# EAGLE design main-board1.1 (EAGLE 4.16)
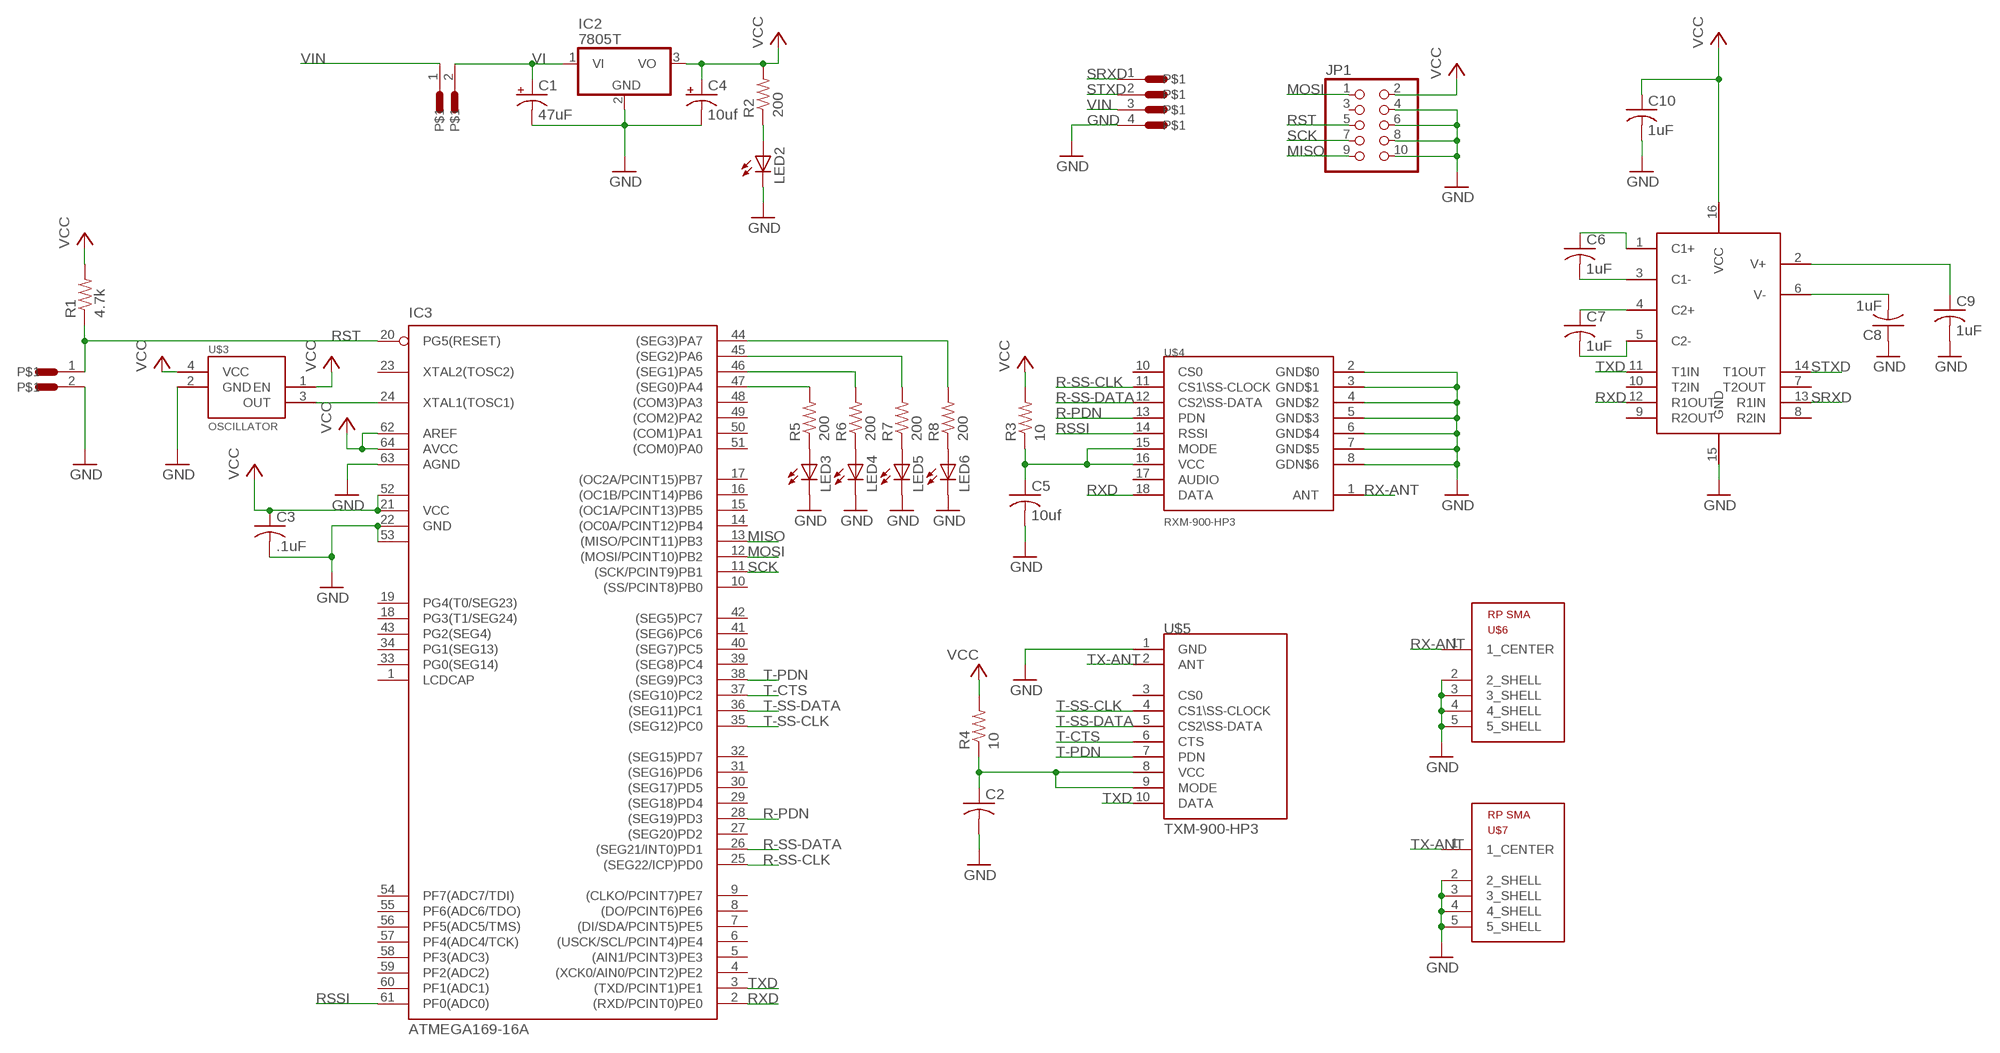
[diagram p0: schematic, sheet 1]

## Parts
C1  47uF  CPOL-USE  [PANASONIC_E]
C2  C-USC1206  [C1206]
C3  .1uF  C-USC0603  [C0603]
C4  10uf  CPOL-USB  [PANASONIC_B]
C5  10uf  C-USC1206  [C1206]
C6  1uF  C-USC0603  [C0603]
C7  1uF  C-USC0603  [C0603]
C8  1uF  C-USC0603  [C0603]
C9  1uF  C-USC0603  [C0603]
C10  1uF  C-USC0603  [C0603]
IC2  7805T  [TO220H]
IC3  ATMEGA169-16A  [TQFP64]
JP1  PINHD-2X5  [2X05]
LED2  LED5MM  [LED5MM]
LED3  LED5MM  [LED5MM]
LED4  LED5MM  [LED5MM]
LED5  LED5MM  [LED5MM]
LED6  LED5MM  [LED5MM]
R1  4.7k  R-US_R0603  [R0603]
R2  200  R-US_R0603  [R0603]
R3  10  R-US_R0603  [R0603]
R4  10  R-US_R0603  [R0603]
R5  200  R-US_R0603  [R0603]
R6  200  R-US_R0603  [R0603]
R7  200  R-US_R0603  [R0603]
R8  200  R-US_R0603  [R0603]
U$1  JST_PA_2  [JST_PA_2]
U$2  JST_PA_2  [JST_PA_2]
U$3  OSCILLATOR  [7X5MM]
U$4  RXM-900-HP3  [RXM-900-HP3]
U$5  TXM-900-HP3  [TXM-900-HP3]
U$6  RP_SMA_TH  [RPSMA_TH]
U$7  RP_SMA_TH  [RPSMA_TH]
U$8  JST_PA_4  [JST_PA_4]
U$9  MAX232-SO16  [SO16]

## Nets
GND: C1.- C2.2 C3.2 C4.- C5.2 C8.1 C9.2 C10.2 IC2.2(GND) IC3.22(GND) IC3.53(GND1) IC3.63(AGND) JP1.4 JP1.6 JP1.8 JP1.10 LED2.K(C) LED3.K(C) LED4.K(C) LED5.K(C) LED6.K(C) U$1.2 U$3.2(GND) U$4.2(GND$0) U$4.3(GND$1) U$4.4(GND$2) U$4.5(GND$3) U$4.6(GND$4) U$4.7(GND$5) U$4.8(GDN$6) U$5.1(GND) U$6.2(2_SHELL) U$6.3(3_SHELL) U$6.4(4_SHELL) U$6.5(5_SHELL) U$7.2(2_SHELL) U$7.3(3_SHELL) U$7.4(4_SHELL) U$7.5(5_SHELL) U$8.4 U$9.15(GND)
MISO: IC3.13((MISO/PCINT11)PB3) JP1.9
MOSI: IC3.12((MOSI/PCINT10)PB2) JP1.1
N$1: LED2.A R2.1
N$2: C6.1 U$9.1(C1+)
N$3: C6.2 U$9.3(C1-)
N$4: C7.1 U$9.4(C2+)
N$5: C7.2 U$9.5(C2-)
N$6: C9.1 U$9.2(V+)
N$7: C8.2 U$9.6(V-)
N$8: LED3.A R5.1
N$9: C2.1 R4.1 U$5.8(VCC) U$5.9(MODE)
N$10: LED4.A R6.1
N$11: LED5.A R7.1
N$12: C5.1 R3.1 U$4.15(MODE) U$4.16(VCC)
N$13: LED6.A R8.1
N$14: IC3.47((SEG0)PA4) R5.2
N$15: IC3.46((SEG1)PA5) R6.2
N$16: IC3.45((SEG2)PA6) R7.2
N$17: IC3.44((SEG3)PA7) R8.2
N$18: IC3.24(XTAL1(TOSC1)) U$3.3(OUT)
R-PDN: IC3.28((SEG19)PD3) U$4.13(PDN)
R-SS-CLK: IC3.25((SEG22/ICP)PD0) U$4.11(CS1\SS-CLOCK)
R-SS-DATA: IC3.26((SEG21/INT0)PD1) U$4.12(CS2\SS-DATA)
RSSI: IC3.61(PF0(ADC0)) U$4.14(RSSI)
RST: IC3.20(PG5(RESET)) JP1.5 R1.1 U$1.1
RX-ANT: U$4.1(ANT) U$6.1(1_CENTER)
RXD: IC3.2((RXD/PCINT0)PE0) U$4.18(DATA) U$9.12(R1OUT)
SCK: IC3.11((SCK/PCINT9)PB1) JP1.7
SRXD: U$8.1 U$9.13(R1IN)
STXD: U$8.2 U$9.14(T1OUT)
T-CTS: IC3.37((SEG10)PC2) U$5.6(CTS)
T-PDN: IC3.38((SEG9)PC3) U$5.7(PDN)
T-SS-CLK: IC3.35((SEG12)PC0) U$5.4(CS1\SS-CLOCK)
T-SS-DATA: IC3.36((SEG11)PC1) U$5.5(CS2\SS-DATA)
TX-ANT: U$5.2(ANT) U$7.1(1_CENTER)
TXD: IC3.3((TXD/PCINT1)PE1) U$5.10(DATA) U$9.11(T1IN)
VCC: C3.1 C4.+ C10.1 IC2.3(VO) IC3.21(VCC) IC3.52(VCC1) IC3.62(AREF) IC3.64(AVCC) JP1.2 R1.2 R2.2 R3.2 R4.2 U$3.1(EN) U$3.4(VCC) U$9.16(VCC)
VI: C1.+ IC2.1(VI) U$2.2
VIN: U$2.1 U$8.3
Unconnected: IC3.1(LCDCAP) IC3.4((XCK0/AIN0/PCINT2)PE2) IC3.5((AIN1/PCINT3)PE3) IC3.6((USCK/SCL/PCINT4)PE4) IC3.7((DI/SDA/PCINT5)PE5) IC3.8((DO/PCINT6)PE6) IC3.9((CLKO/PCINT7)PE7) IC3.10((SS/PCINT8)PB0) IC3.14((OC0A/PCINT12)PB4) IC3.15((OC1A/PCINT13)PB5) IC3.16((OC1B/PCINT14)PB6) IC3.17((OC2A/PCINT15)PB7) IC3.18(PG3(T1/SEG24)) IC3.19(PG4(T0/SEG23)) IC3.23(XTAL2(TOSC2)) IC3.27((SEG20)PD2) IC3.29((SEG18)PD4) IC3.30((SEG17)PD5) IC3.31((SEG16)PD6) IC3.32((SEG15)PD7) IC3.33(PG0(SEG14)) IC3.34(PG1(SEG13)) IC3.39((SEG8)PC4) IC3.40((SEG7)PC5) IC3.41((SEG6)PC6) IC3.42((SEG5)PC7) IC3.43(PG2(SEG4)) IC3.48((COM3)PA3) IC3.49((COM2)PA2) IC3.50((COM1)PA1) IC3.51((COM0)PA0) IC3.54(PF7(ADC7/TDI)) IC3.55(PF6(ADC6/TDO)) IC3.56(PF5(ADC5/TMS)) IC3.57(PF4(ADC4/TCK)) IC3.58(PF3(ADC3)) IC3.59(PF2(ADC2)) IC3.60(PF1(ADC1)) JP1.3 U$4.10(CS0) U$4.17(AUDIO) U$5.3(CS0) U$9.7(T2OUT) U$9.8(R2IN) U$9.9(R2OUT) U$9.10(T2IN)

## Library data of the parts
C1 C4 = rcl:CPOL-US: POLARIZED CAPACITOR, American symbol
C2 C3 C5-C10 = rcl:C-US: CAPACITOR, American symbol
IC2 = linear:78*: Positive VOLTAGE REGULATOR Source: http://cache.national.com/ds/LM/LM78L05.pdf http://www.fairchildsemi.com/ds/LM/LM7805.pdf
IC3 = avr:ATMEGA169: MICROCONTROLLER 16 Kbytes FLASH 1 Kbytes SRAM 512 bytes EEPROM USART 8-channel 10 bit ADC 4x25 Segment LCD Driver
JP1 = pinhead:PINHD-2X5: PIN HEADER
LED2-LED6 = led:LED: LED
R1-R8 = rcl:R-US_: RESISTOR, American symbol
U$1 U$2 = jst_pa:JST_PA_2
U$3 = misc-personal:OSCILLATOR
U$4 = HP3:RXM-900-HP3
U$5 = HP3:TXM-900-HP3
U$6 U$7 = linx:RP_SMA_TH
U$8 = jst_pa:JST_PA_4
U$9 = max232:MAX232-SO16

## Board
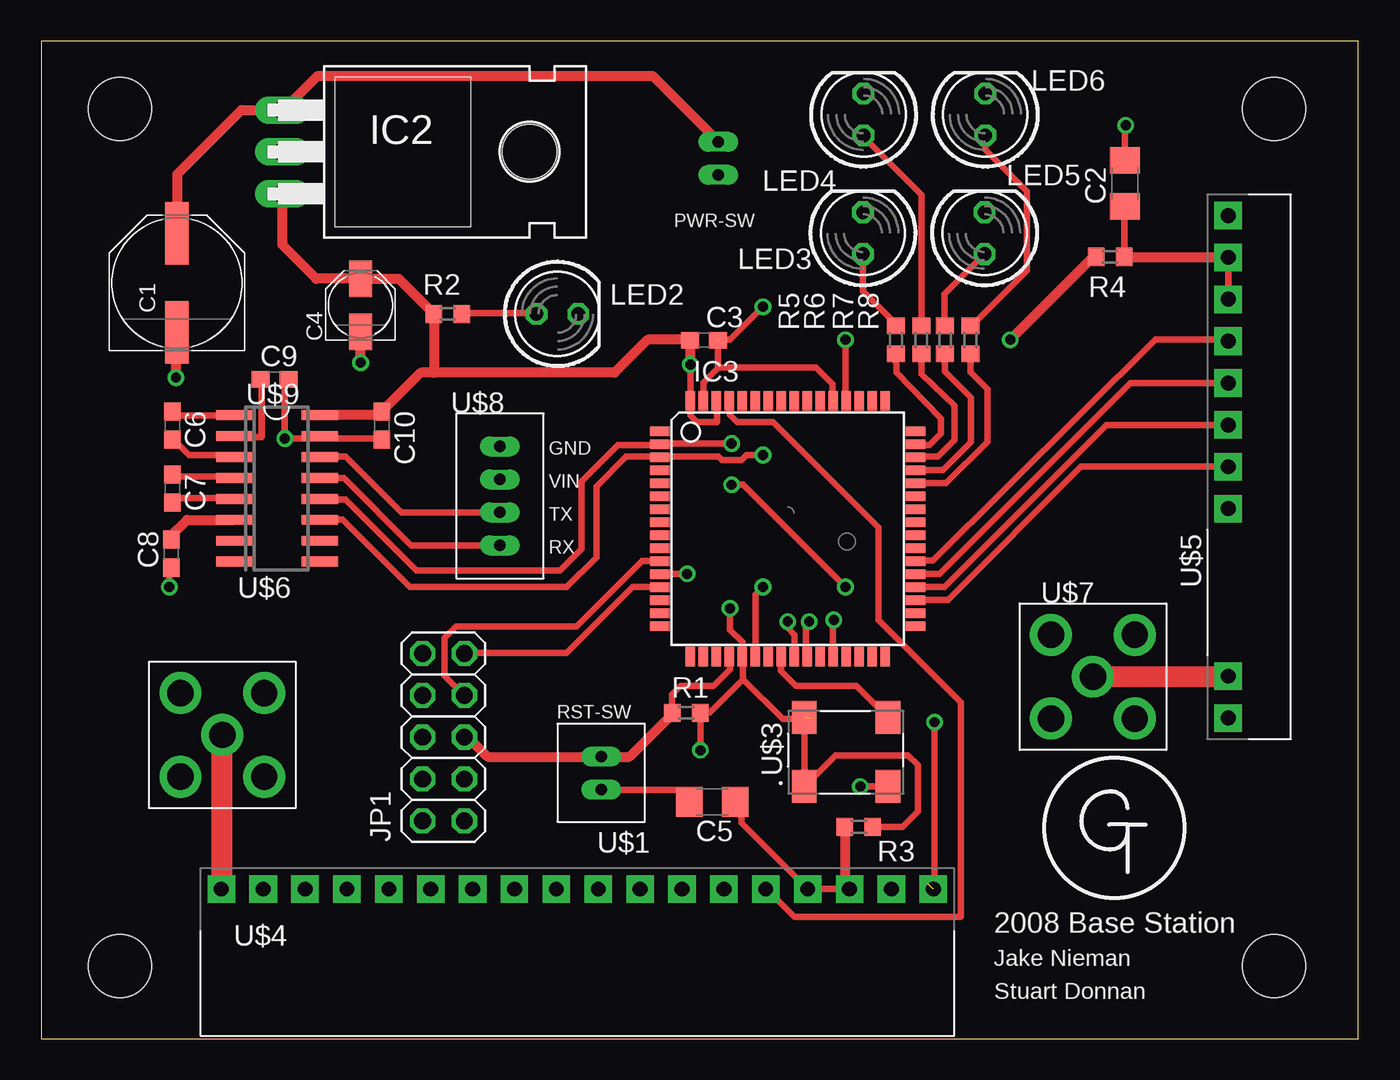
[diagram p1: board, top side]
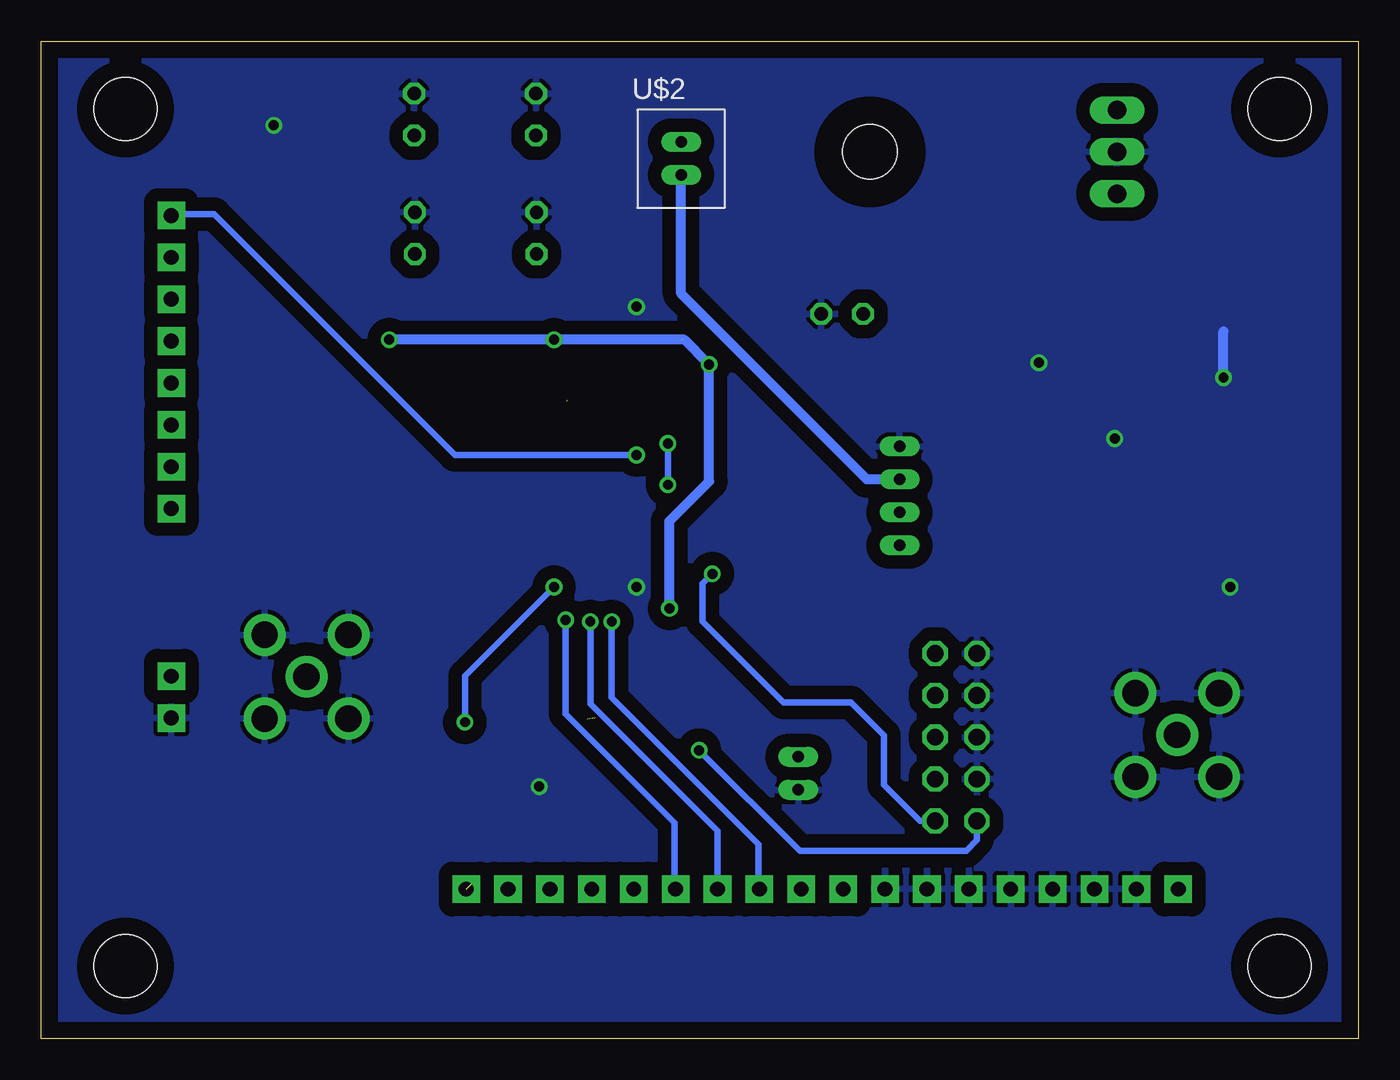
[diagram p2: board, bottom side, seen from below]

Size 79.87 x 60.49 mm. Coordinates in mm from the lower left corner, seen from the top.
Outline: 0,0 79.87,0 79.87,60.49 0,60.49 0,0
Copper layers (1*16): Top 0.035mm / dielectric 1.5mm / Bottom 0.035mm
Design rules "4pcb": minimum track width 6mil, minimum drill 15mil, track to track 6mil, track to pad 6mil, pad to pad 6mil, via to via 6mil, smd to smd 6mil, copper to edge 40mil, drill to drill 6mil, minimum pad ring 10mil, minimum via ring 8mil, stop-mask expansion 6mil, vias tented up to drill 0mil, thermal gap 10mil
Holes 3.82 mm at 4.77,56.39 4.77,4.39 74.77,4.39 74.77,56.39

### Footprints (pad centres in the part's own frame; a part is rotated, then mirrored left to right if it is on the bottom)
PANASONIC_E = smd 3.8 x 1.4: + 3,0; - -3,0
C1206 = smd 1.6 x 1.8: 1 -1.4,0; 2 1.4,0
C0603 = smd 1.1 x 1: 1 -0.85,0; 2 0.85,0
PANASONIC_B = smd 2.2 x 1.4: + 1.6,0; - -1.6,0
TO220H = drill 1.118 long: 1 -2.54,-10.16; 2 0,-10.16; 3 2.54,-10.16 | hole 3.302: 0,4.826
TQFP64 = smd 1.194 x 0.559: 1 -7.76,5.905; 2 -7.76,5.118; 3 -7.76,4.331; 4 -7.76,3.543; 5 -7.76,2.756; 6 -7.76,1.968; 7 -7.76,1.181; 8 -7.76,0.394; 9 -7.76,-0.394; 10 -7.76,-1.181; 11 -7.76,-1.968; 12 -7.76,-2.756; 13 -7.76,-3.543; 14 -7.76,-4.331; 15 -7.76,-5.118; 16 -7.76,-5.905; 33 7.76,-5.905; 34 7.76,-5.118; 35 7.76,-4.331; 36 7.76,-3.543; 37 7.76,-2.756; 38 7.76,-1.968; 39 7.76,-1.181; 40 7.76,-0.394; 41 7.76,0.394; 42 7.76,1.181; 43 7.76,1.968; 44 7.76,2.756; 45 7.76,3.543; 46 7.76,4.331; 47 7.76,5.118; 48 7.76,5.905 | smd 0.559 x 1.194: 17 -5.905,-7.76; 18 -5.118,-7.76; 19 -4.331,-7.76; 20 -3.543,-7.76; 21 -2.756,-7.76; 22 -1.968,-7.76; 23 -1.181,-7.76; 24 -0.394,-7.76; 25 0.394,-7.76; 26 1.181,-7.76; 27 1.968,-7.76; 28 2.756,-7.76; 29 3.543,-7.76; 30 4.331,-7.76; 31 5.118,-7.76; 32 5.905,-7.76; 49 5.905,7.76; 50 5.118,7.76; 51 4.331,7.76; 52 3.543,7.76; 53 2.756,7.76; 54 1.968,7.76; 55 1.181,7.76; 56 0.394,7.76; 57 -0.394,7.76; 58 -1.181,7.76; 59 -1.968,7.76; 60 -2.756,7.76; 61 -3.543,7.76; 62 -4.331,7.76; 63 -5.118,7.76; 64 -5.905,7.76
2X05 = drill 1.016 octagon: 1 -5.08,-1.27; 2 -5.08,1.27; 3 -2.54,-1.27; 4 -2.54,1.27; 5 0,-1.27; 6 0,1.27; 7 2.54,-1.27; 8 2.54,1.27; 9 5.08,-1.27; 10 5.08,1.27
LED5MM = drill 0.813 octagon: A -1.27,0; K 1.27,0
R0603 = smd 1 x 1.1: 1 -0.85,0; 2 0.85,0
JST_PA_2 = drill 0.7 long: 1 13.35,0; 2 11.35,0
7X5MM = smd 1.5 x 2: 1 0,-4.2; 2 5.08,-4.2; 3 5.08,0; 4 0,0
RXM-900-HP3 = drill 0.9 pad 1.676 square: 1 0,0; 2 2.54,0; 3 5.08,0; 4 7.62,0; 5 10.16,0; 6 12.7,0; 7 15.24,0; 8 17.78,0; 9 20.32,0; 10 22.86,0; 11 25.4,0; 12 27.94,0; 13 30.48,0; 14 33.02,0; 15 35.56,0; 16 38.1,0; 17 40.64,0; 18 43.18,0
TXM-900-HP3 = drill 0.9 pad 1.676 square: 1 0,0; 2 2.54,0; 3 12.7,0; 4 15.24,0; 5 17.78,0; 6 20.32,0; 7 22.86,0; 8 25.4,0; 9 27.94,0; 10 30.48,0
RPSMA_TH = drill 1.6 pad 2.54 round: 1 0,0; 2 2.54,2.54; 3 2.54,-2.54; 4 -2.54,-2.54; 5 -2.54,2.54
JST_PA_4 = drill 0.7 long: 1 3,0; 2 1,0; 3 -1,0; 4 -3,0
SO16 = smd 0.6 x 2.2: 1 -4.445,-2.6; 2 -3.175,-2.6; 3 -1.905,-2.6; 4 -0.635,-2.6; 5 0.635,-2.6; 6 1.905,-2.6; 7 3.175,-2.6; 8 4.445,-2.6; 9 4.445,2.6; 10 3.175,2.6; 11 1.905,2.6; 12 0.635,2.6; 13 -0.635,2.6; 14 -1.905,2.6; 15 -3.175,2.6; 16 -4.445,2.6

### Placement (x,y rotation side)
C1  8.23,45.83 90 top
C2  65.72,51.87 90 top
C3  40.19,42.35 0 top
C4  19.36,44.47 90 top
C5  40.69,14.36 180 top
C6  7.95,37.18 270 top
C7  7.95,33.37 270 top
C8  7.89,29.41 90 top
C9  14.16,39.99 0 top
C10  20.65,37.18 270 top
IC2  24.79,53.78 270 top
IC3  45.27,30.92 0 top
JP1  24.39,18.28 90 top
LED2  31.3,43.95 0 top
LED3  49.83,48.85 90 top
LED4  49.87,56.05 90 top
LED5  57.21,48.85 90 top
LED6  57.25,56.05 90 top
R1  39.11,19.76 0 top
R2  24.65,43.95 180 top
R3  49.58,12.84 0 top
R4  64.81,47.41 180 top
R5  51.83,42.37 270 top
R6  53.37,42.37 270 top
R7  54.81,42.37 270 top
R8  56.35,42.37 270 top
U$1  33.96,3.74 90 top
U$2  41.06,65.74 270 bottom
U$3  46.27,19.49 0 top
U$4  10.92,9.07 0 top
U$5  71.98,19.44 90 top
U$6  10.98,18.42 180 top
U$7  63.78,21.95 0 top
U$8  27.82,32.92 270 top
U$9  14.3,33.37 270 top

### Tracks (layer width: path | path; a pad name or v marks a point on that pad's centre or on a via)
GND  (via drill 0.6)  (2 unrouted)
  Top 0.254: 40.81,42.35 40.77,42.39 41,42.39 | IC3.63 40.17,38.7 | 16.77,36.39 16.77,36.41 U$9.15 16.75,36.39 | C10.2 20.59,36.39 | 7.77,28.39 7.77,28.44 C8.1 | 39.27,14.99 39.25,15.01 | 41.07,40.69 41.04,40.72
  Top 0.406: 40.17,38.7 40.17,39.79 41.07,40.69 46.97,40.69 47.97,39.69 47.97,38.74 | v49.67,15.29 U$3.2 | 39.27,15.09 39.27,14.99 39.27,14.36 C5.2 | 41.04,40.72 C3.2 | 39.27,15.09 39.27,15.06 | U$1.2 39.27,15.09 | 14.77,39.75 C9.2 14.97,39.99 14.77,39.79 v14.77,36.39 16.77,36.39 | IC3.22 43.3,26.92 v43.77,27.39 | 16.77,36.39 16.9,36.52 U$9.15 | C10.2 20.71,36.33 20.77,36.39 16.77,36.39 | 41,42.39 41.77,42.39 v43.77,44.39 | C2.2 65.72,55.34 v65.77,55.39 | 7.77,28.39 v7.77,27.39
  Top 0.61: 20.77,36.39 20.77,36.33 C10.2 | C9.2 15.07,39.99 | 19.47,42.89 19.45,42.87 C4.- | C1.- 8.17,42.83 v8.17,40.09 | C4.- 19.37,42.99 | v19.37,40.99 C4.-
  Bottom 0.254: U$1.2
  Bottom 0.61: v8.17,40.09 8.17,42.89
  pour Bottom (isolate 0.813): -0.23,60.39 -0.23,0.39 79.77,0.39 79.77,60.39
MISO
  Top 0.254: JP1.9 25.66,23.2 25.67,23.19 25.87,23.39
  Top 0.406: IC3.13 35.86,27.38 31.87,23.39 25.87,23.39
MOSI  (via drill 0.6)
  Top 0.406: IC3.12 37.54,28.19 v39.17,28.19
  Bottom 0.406: v39.17,28.19 39.77,27.59 39.77,25.29 34.87,20.39 30.77,20.39 28.77,18.39 28.77,15.39 26.57,13.19 JP1.1
N$1
  Top 0.254: 25.47,43.99 25.47,43.98 R2.1 | 29.99,43.99 LED2.A
  Top 0.406: 25.47,43.99 29.99,43.99
N$2
  Top 0.254: 11.67,37.79 U$9.1
  Top 0.406: C6.1 7.97,38.01 7.97,37.79 11.67,37.79
N$3
  Top 0.254: 11.58,35.39 U$9.3 | 7.77,36.39 7.89,36.39 C6.2
  Top 0.406: C6.2 7.95,36.37 7.97,36.39 8.97,35.39 11.58,35.39
N$4
  Top 0.254: C7.1 8.08,34.09 | 11.62,34.09 U$9.4
  Top 0.406: C7.1 7.95,34.11 7.97,34.09 11.62,34.09
N$5
  Top 0.254: 8.07,32.79 8.07,32.64 C7.2 | 11.64,32.79 U$9.5
  Top 0.406: C7.2 7.95,32.57 8.17,32.79 11.64,32.79
N$6
  Top 0.254: 11.67,36.49 11.67,36.52 U$9.2
  Top 0.406: 11.67,36.49 13.37,36.49 13.37,39.93 C9.1
N$7
  Top 0.61: C8.2 7.77,30.39 8.84,31.47 U$9.6
N$8
  Top 0.406: R5.1 51.83,43.33 49.83,45.33 LED3.A
N$9
  Top 0.254: 65.66,47.5 65.77,47.39 | 65.66,47.5 R4.1 65.66,47.8 65.67,47.79 65.7,47.82 | 65.66,47.5 65.65,47.51
  Top 0.406: 71.77,47.39 71.78,47.38 U$5.9 71.98,44.6 | 71.98,44.6 U$5.8 | 71.98,44.6 71.77,44.39 | R4.1 65.67,47.81 65.67,47.79 65.67,50.47 C2.1
  Top 0.61: 65.77,47.39 71.77,47.39
N$10
  Top 0.406: LED4.A 49.87,54.69 53.37,51.19 R6.1
N$11
  Top 0.406: R7.1 54.77,43.26 54.77,45.14 LED5.A
N$12
  Top 0.254: U$4.15 | U$4.16 48.99,9.07 48.97,9.09 48.95,9.07
  Top 0.406: 42.47,13.09 42.45,13.71 | 42.47,13.09 U$4.15 | U$4.15 48.95,9.07 | C5.1 42.47,14.36 42.47,13.09
  Top 0.61: U$4.16 48.77,9.32 48.77,12.79 R3.1
N$13
  Top 0.406: LED6.A 57.25,53.91 59.77,51.39 59.77,46.59 56.37,43.19 R8.1
N$14
  Top 0.254: IC3.47 53.03,36.09
  Top 0.406: IC3.47 53.07,36 53.07,35.99 53.87,35.99 54.57,36.69 54.57,37.59 51.87,40.39 51.83,41.45 R5.2
N$15
  Top 0.254: 53.17,35.29 53.03,35.15 IC3.46 53.07,35.29
  Top 0.406: R6.2 53.37,40.29 55.37,38.39 55.37,36.29 54.37,35.29 53.27,35.29 53.17,35.19 53.11,35.25 IC3.46
N$16
  Top 0.406: R7.2 54.81,40.45 56.37,38.89 56.37,36.19 54.67,34.49 53.17,34.49 53.14,34.46 IC3.45
N$17
  Top 0.254: 52.97,33.59 53.03,33.65 IC3.44
  Top 0.406: R8.2 56.35,40.41 57.37,39.39 57.37,36.19 54.87,33.69 53.07,33.69 53.06,33.68 IC3.44
N$18
  Top 0.254: IC3.24 44.9,23.16 44.97,23.09 44.87,22.99
  Top 0.406: U$3.3 49.45,21.39 45.77,21.39 44.87,22.29 44.87,22.99
R-PDN  (via drill 0.6)
  Top 0.254: IC3.28 48.07,23.2 v48.07,25.39
  Top 0.406: IC3.28 48.03,25.39 47.77,25.39
  Bottom 0.254: 41.47,9.09 41.42,9.09 U$4.13
  Bottom 0.406: 41.47,9.09 41.47,13.09 48.07,19.69 v48.07,25.39 48.07,25.49
R-SS-CLK  (via drill 0.6)
  Top 0.254: IC3.25 | v45.27,25.29 45.27,24.89
  Top 0.406: IC3.25 45.67,24.49 45.27,24.89
  Bottom 0.254: 36.37,8.99 36.37,9.02 U$4.11
  Bottom 0.406: 36.37,9.02 36.37,11.79 45.27,20.69 v45.27,25.29
R-SS-DATA  (via drill 0.6)
  Top 0.254: 46.37,23.24 IC3.26 | 46.37,25.19 46.47,25.29 v46.57,25.29
  Top 0.406: 46.37,25.19 46.37,23.24
  Bottom 0.254: U$4.12
  Bottom 0.406: U$4.12 38.87,12.59 46.57,20.29 v46.57,25.29
RSSI
  Top 0.254: 41.77,38.64 IC3.61 | 43.97,9.09 U$4.14
  Top 0.406: 41.77,38.64 41.77,37.8 42.18,37.39 44.37,37.39 50.77,30.99 50.77,25.39 55.77,20.39 55.77,7.39 45.67,7.39 43.97,9.09
RST
  Top 0.254: 38.27,19.69 38.26,19.7 R1.1 | IC3.20 41.77,23.2 | 25.77,18.39 JP1.5
  Top 0.406: R1.1 38.26,20.88 38.77,21.39 40.77,21.39 41.77,22.39 41.77,23.39 41.73,23.35 IC3.20
  Top 0.61: 38.27,19.69 35.67,17.09 U$1.1 27.07,17.09 25.77,18.39
RX-ANT
  Top 1.27: U$4.1 10.97,9.07 10.97,15.42 U$6.1
RXD  (via drill 0.6)  (2 unrouted)
  Top 0.254: 37.56,36.09 IC3.2 37.56,35.99 37.57,35.99 | 16.95,32.79 U$9.12 16.9,32.82 16.97,32.89 17.07,32.79
  Top 0.406: 37.56,36.09 v41.87,36.09 | 37.56,35.99 34.97,35.99 32.77,33.79 32.77,29.69 31.47,28.39 22.77,28.39 18.47,32.69 16.95,32.69 U$9.12 | v41.87,33.59 42.57,33.59 v48.77,27.39 | 54.17,8.99 U$4.18 | v54.17,19.19 54.17,8.99 | 54.17,8.99 54.27,8.89
  Bottom 0.254: 53.78,9.39 53.77,9.39 | 54.07,9.09 U$4.18
  Bottom 0.406: v41.87,36.09 v41.87,33.59 | v48.77,27.39 54.17,21.99 v54.17,19.19
SCK
  Top 0.254: 25.67,20.79 25.66,20.8 JP1.7
  Top 0.406: IC3.11 36.43,28.95 32.47,24.99 25.17,24.99 24.47,24.29 24.47,21.99 25.66,20.8
SRXD
  Top 0.254: 16.97,33.99 16.95,34.01 U$9.13
  Top 0.406: U$9.13 16.98,34.01 17.07,34.09 17.17,33.99 18.37,33.99 22.44,29.92 U$8.1
STXD
  Top 0.254: U$9.14 16.97,35.19 17.07,35.29
  Top 0.406: 18.57,35.19 18.47,35.29 16.97,35.29 16.95,35.27 U$9.14 | 18.57,35.19 18.84,34.92 | U$8.2 21.84,31.92 18.57,35.19
T-CTS
  Top 0.254: IC3.37 53.06,28.19
  Top 0.406: 53.06,28.19 54.47,28.19 66.04,39.76 U$5.6
T-PDN
  Top 0.254: 53.07,28.99 53.07,28.91 IC3.38 | 71.89,42.39 U$5.7
  Top 0.406: 53.07,28.99 54.07,28.99 67.57,42.39 71.89,42.39
T-SS-CLK
  Top 0.254: IC3.35
  Top 0.406: IC3.35 54.97,26.59 63.06,34.68 U$5.4
T-SS-DATA
  Top 0.254: IC3.36 53.04,27.39
  Top 0.406: 53.04,27.39 54.77,27.39 64.6,37.22 U$5.5
TX-ANT
  Top 1.27: U$5.2 | U$5.2 | U$7.1 71.97,21.95 U$5.2
TXD  (via drill 0.6)
  Top 0.254: 37.55,35.29 IC3.3 37.47,35.29 37.55,35.29 | 37.55,35.29 37.65,35.39 | 16.97,31.59 16.97,31.54 U$9.11 16.97,31.39 17.07,31.49
  Top 0.406: v43.77,35.39 42.77,35.39 42.47,35.09 41.27,35.09 41.07,35.29 37.47,35.29 35.47,35.29 33.67,33.49 33.67,29.19 31.87,27.39 22.37,27.39 18.27,31.49 16.88,31.49 | 16.88,31.49 16.87,31.49 | U$9.11 16.88,31.49
  Bottom 0.406: U$5.10 71.98,49.98 71.97,49.99 69.37,49.99 54.77,35.39 v43.77,35.39
VCC  (via drill 0.6)  (1 unrouted)
  Top 0.254: IC3.64 39.37,38.59 | IC3.64 | 39.37,42.32 C3.1 39.37,42.38 39.37,42.39 | 48.77,38.39 48.77,38.64 IC3.52 | 42.57,23.1 IC3.21 | 23.87,43.89 R2.2 | 23.87,43.89 23.83,43.85 | 23.86,40.39 23.77,40.39 | 20.67,37.89 20.65,37.91 C10.1 | U$9.16 16.95,37.81 16.97,37.79 17.21,37.83 | IC3.62 40.94,38.62 40.97,38.59 40.97,38.39 | IC3.64 39.37,39.79 | R1.2 39.99,19.79 | 23.87,43.89 23.77,43.92 R2.2 | R2.2 23.83,43.95 23.86,43.98 23.87,43.99
  Top 0.406: v39.37,40.89 IC3.64 | v48.77,42.39 48.77,38.64 | U$3.4 U$3.1 48.17,17.19 52.57,17.19 53.17,16.59 53.17,13.79 52.77,13.39 | 42.57,21.79 42.57,23.1 | 42.57,21.79 44.97,19.39 46.77,19.39 | IC3.21 42.51,24.05 41.77,24.79 v41.77,26.09 | 20.67,37.99 20.67,37.89 | IC3.64 39.36,37.8 39.77,37.39 40.97,37.39 40.97,38.39 | 39.99,19.79 40.57,19.79 42.57,21.79 | 52.77,13.39 52.53,13.15 | 39.27,42.39 39.31,42.35 C3.1 | 63.96,47.58 R4.2 | R1.2 39.97,19.79 | R1.2 | R3.2 52.22,12.84 52.77,13.39 | v39.97,17.49 R1.2
  Top 0.61: v39.37,40.89 39.37,42.32 | 23.86,43.98 23.86,40.39 34.77,40.39 36.77,42.39 39.27,42.39 | 17.21,37.83 20.67,37.83 20.67,37.99 20.67,38.03 C10.1 23.01,40.39 23.77,40.39 | v58.77,42.39 63.96,47.58 | IC2.3 14.63,48.13 16.67,46.09 19.37,46.09 C4.+ 21.69,46.07 R2.2
  Bottom 0.406: JP1.2 23.12,12.04 23.77,11.39 33.87,11.39 v39.97,17.49
  Bottom 0.61: v58.77,42.39 v48.77,42.39 40.87,42.39 v39.37,40.89 39.37,33.79 41.77,31.39 v41.77,26.09
VI
  Top 0.254: 14.7,56.39 14.63,56.39 IC2.1 14.7,56.39 | 14.7,56.39 14.77,56.39
  Top 0.61: U$2.2 37.06,58.39 16.77,58.39 14.77,56.39 | IC2.1 12.14,56.32 8.27,52.45 8.27,49.87 C1.+
VIN
  Bottom 0.406: U$2.1 40.77,52.39 41.07,52.09
  Bottom 0.61: U$8.3 29.8,33.92 41.07,45.19 41.07,52.09

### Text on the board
tPlace: 2008 Base Station | Jake Nieman | Stuart Donnan
tNames: PWR-SW | GND | VIN | TX | RX | RST-SW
